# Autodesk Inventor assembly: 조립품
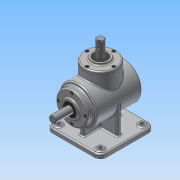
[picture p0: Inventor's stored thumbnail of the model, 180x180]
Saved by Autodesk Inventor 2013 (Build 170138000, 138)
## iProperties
Created: 2015-07
Part Number: 조립품
Document SubType Name: Assembly
Designer: ST5
Author: ST5
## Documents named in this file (14)
- C:\Users\ST5\Desktop\450705V1006\조립품.iam
- C:\Users\ST5\Desktop\450705V1006\본체.ipt
- C:\Users\ST5\Desktop\450705V1006\M4.ipt
- C:\Users\ST5\Desktop\450705V1006\메인 베벨기어.ipt
- C:\Users\ST5\Desktop\450705V1006\메인 축.ipt
- 메인 축.ipt
- C:\Users\ST5\Desktop\450705V1006\베어링 6203.ipt
- C:\Users\ST5\Desktop\450705V1006\서브 베벨기어.ipt
- C:\Users\ST5\Desktop\450705V1006\서브 축.ipt
- 서브 축.ipt
- C:\Users\ST5\Desktop\450705V1006\오일실.ipt
- C:\Users\ST5\Desktop\450705V1006\커버.ipt
- C:\Users\ST5\Desktop\450705V1006\키 4x4.ipt
- C:\Users\ST5\Desktop\450705V1006\키 5x5.ipt
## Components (8 placed, 1 different names)
1. M4:1
2. M4:2
3. M4:3
4. M4:4
5. M4:5
6. M4:6
7. M4:7
8. M4:8
